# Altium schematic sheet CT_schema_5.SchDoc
size 369 x 243 mm
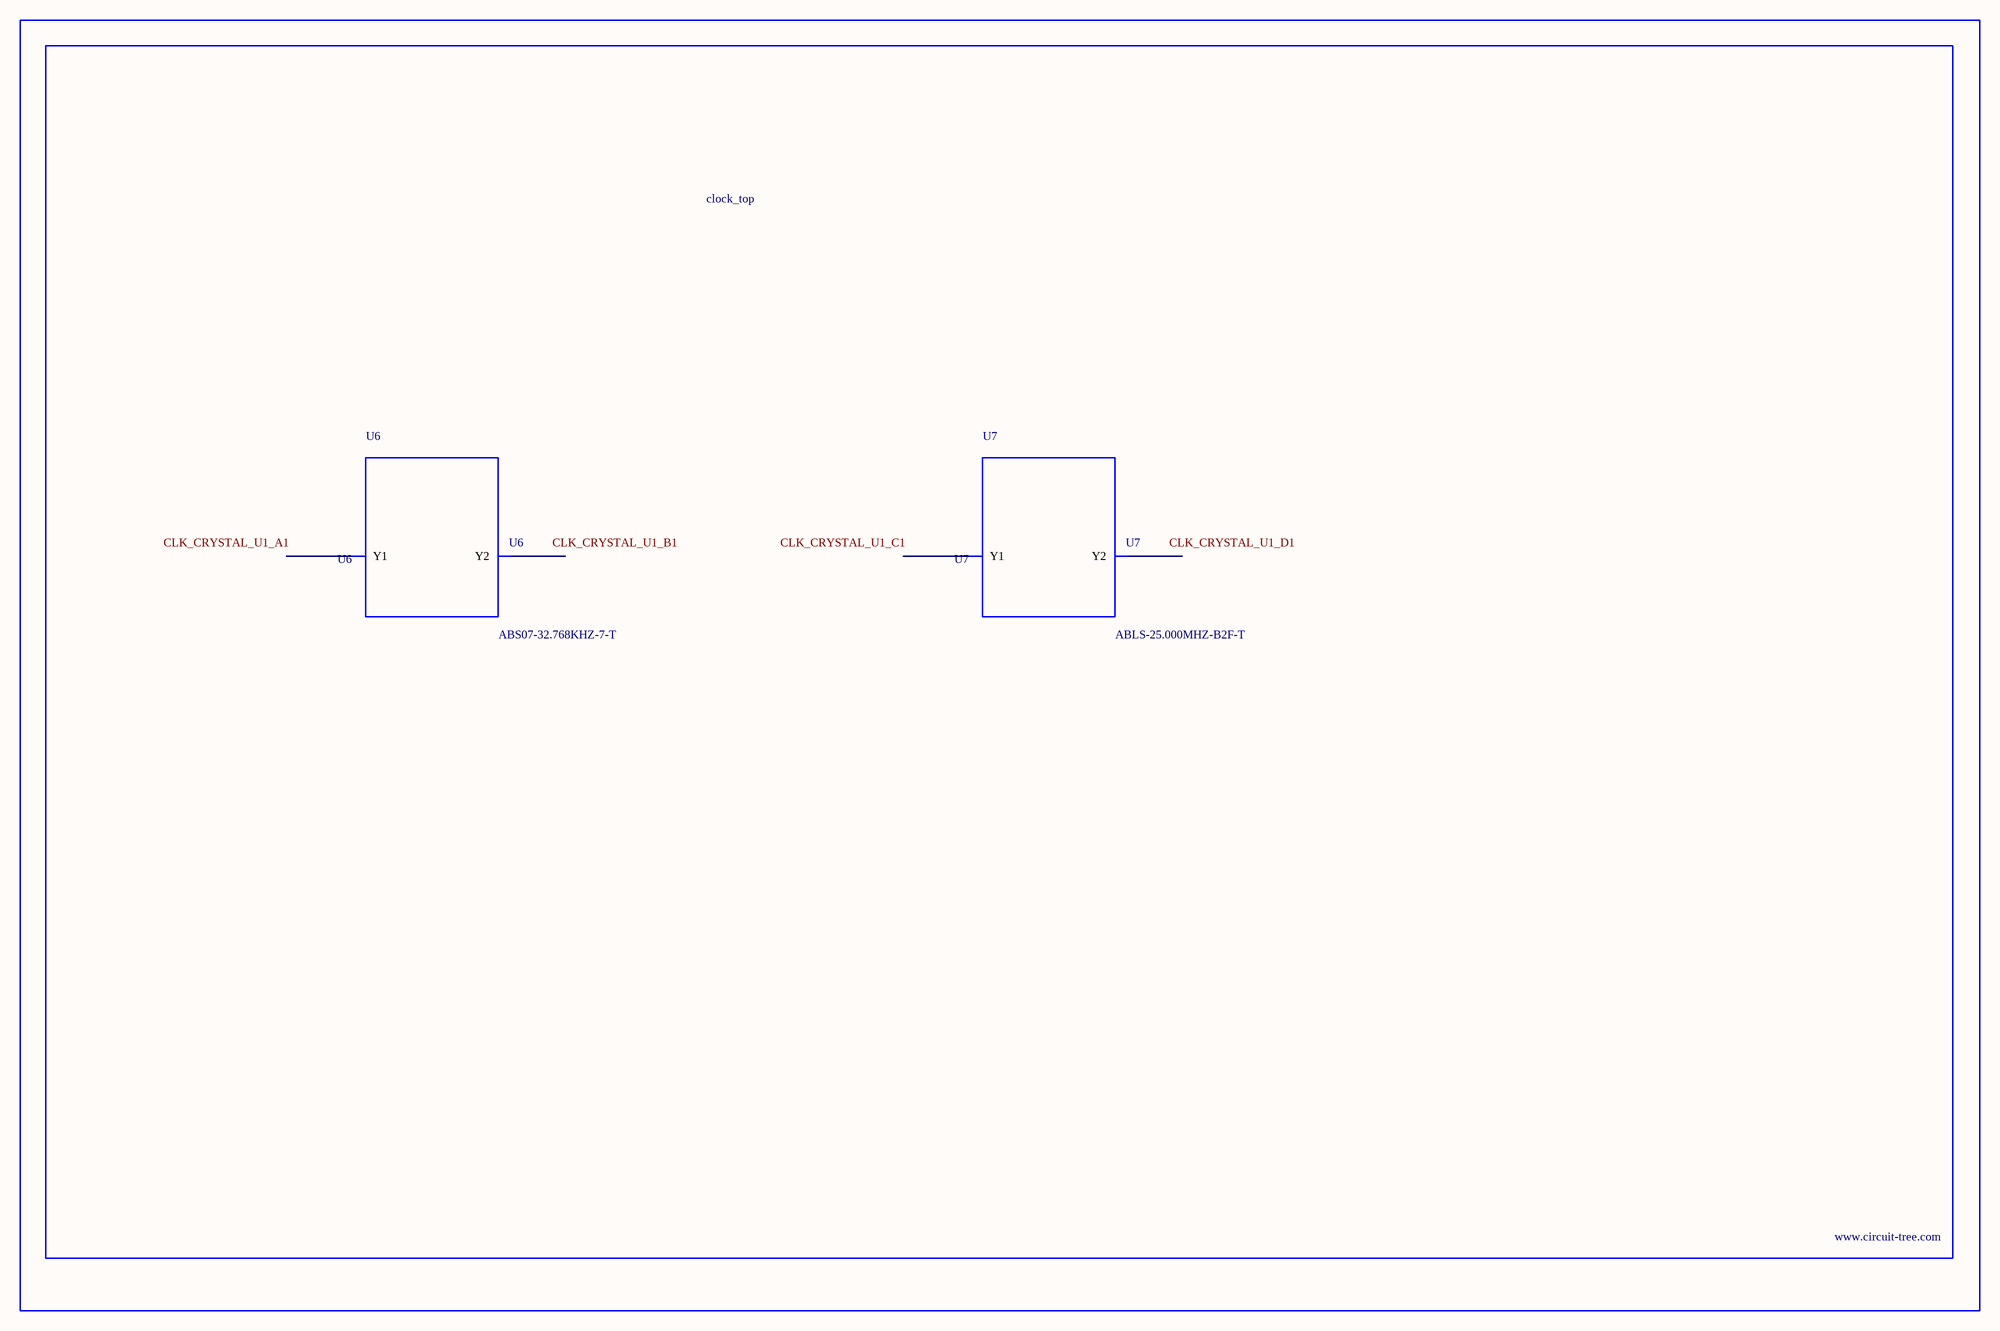
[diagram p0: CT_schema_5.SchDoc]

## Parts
BORDER4  (no value)
U6  ABS07-32.768KHZ-7-T  [ABS07-32.768KHZ-7-T]
U7  ABLS-25.000MHZ-B2F-T  [ABLS-25.000MHZ-B2F-T]

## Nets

Not connected (* = marked no-connect by the designer): U6 1(Y1) 2(Y2); U7 1(Y1) 2(Y2)

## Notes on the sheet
- Labels drawn without touching a wire or pin: CLK_CRYSTAL_U1_A1, CLK_CRYSTAL_U1_B1, CLK_CRYSTAL_U1_C1, CLK_CRYSTAL_U1_D1

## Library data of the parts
BORDER4 = BORDER_PAGE4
